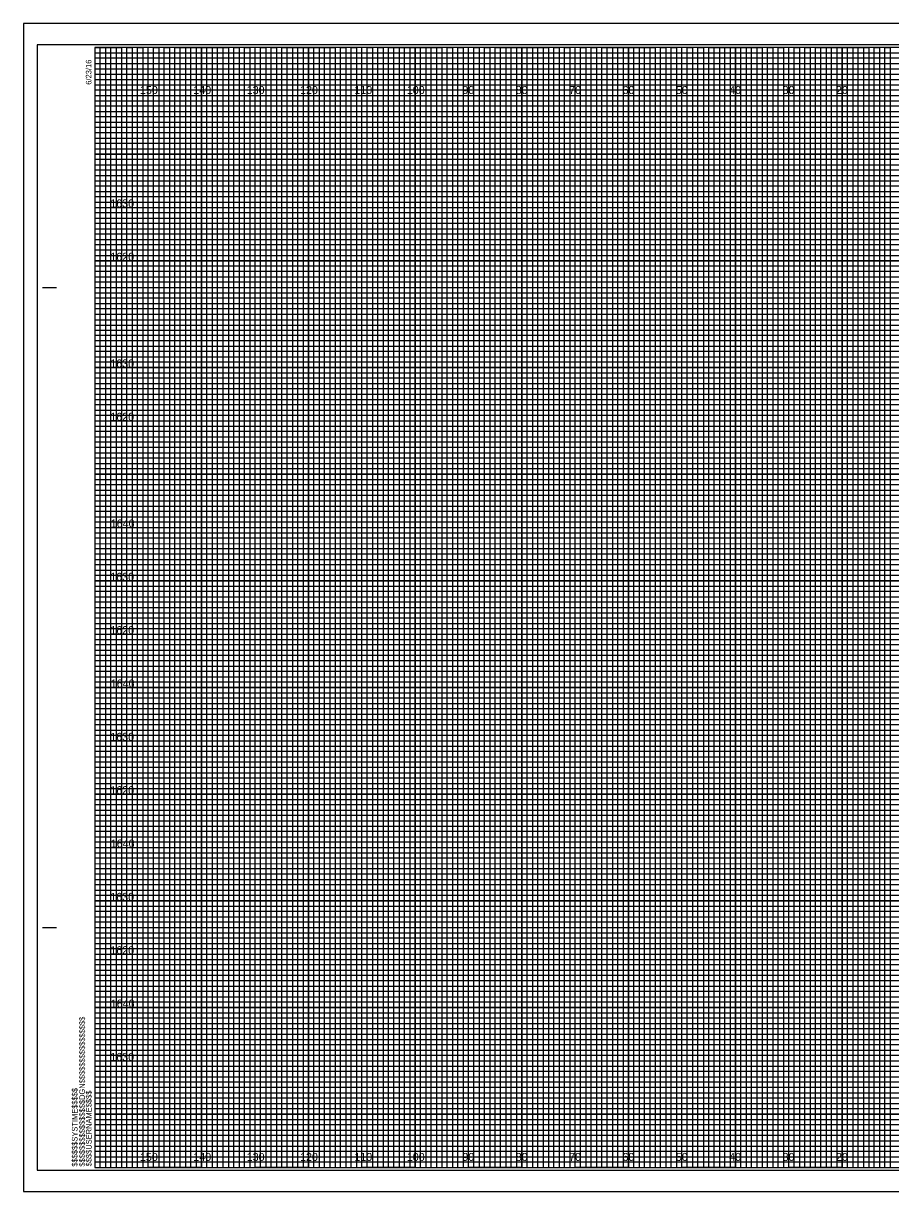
# Model space of a CAD drawing. Extents: x -423 to -87, y -23 to 1516.
# Drawn here: x -423.3 to -260.8, y 417.3 to 636.3 of the extents above; entities that cross this region are included whole.
import ezdxf

# ---------------------------------------------------------------- set-up
doc = ezdxf.new("R2010")
doc.units = 0
for name, color, linetype in [('Prop Horizontal Alignment', 7, 'Continuous'), ('Prop XS DDE', 7, 'Continuous'), ('Prop XS DDE Elevations', 7, 'Continuous'), ('Prop XS DDE Slope Text', 7, 'Continuous'), ('Prop XS Earthwork Shape', 7, 'Continuous'), ('Scratch_Level_3', 7, 'Continuous'), ('Sheet Cross Section Grid Minor 2 CELL', 7, 'Continuous'), ('Sheet Cutting Line CELL', 7, 'Continuous'), ('Sheet DOT Grid CELL', 7, 'Continuous'), ('Sheet Plot Border Inside CELL', 7, 'Continuous'), ('Sheet Plot Border Outside CELL', 7, 'Continuous')]:
    doc.layers.add(name, color=color, linetype=linetype)

msp = doc.modelspace()

# ---------------------------------------------------------------- linework, layer by layer
at = {"layer": 'Prop XS DDE'}
for points in [[(-409.86, 631.8), (-404.86, 631.8), (-404.86, 421.8), (-394.86, 421.8), (-394.86, 631.8), (-384.86, 631.8), (-384.86, 421.8), (-374.86, 421.8), (-374.86, 631.8), (-364.86, 631.8), (-364.86, 421.8), (-354.86, 421.8), (-354.86, 631.8), (-344.86, 631.8), (-344.86, 421.8), (-334.86, 421.8), (-334.86, 631.8), (-324.86, 631.8), (-324.86, 421.8), (-314.86, 421.8), (-314.86, 631.8), (-304.86, 631.8), (-304.86, 421.8), (-294.86, 421.8), (-294.86, 631.8), (-284.86, 631.8), (-284.86, 421.8), (-274.86, 421.8), (-274.86, 631.8), (-264.86, 631.8), (-264.86, 421.8), (-254.86, 421.8)], [(-409.86, 626.8), (-134.86, 626.8)], [(-409.86, 606.8), (-89.86, 606.8), (-89.86, 616.8), (-409.86, 616.8)], [(-409.86, 586.8), (-89.86, 586.8), (-89.86, 596.8), (-409.86, 596.8)], [(-409.86, 566.8), (-89.86, 566.8), (-89.86, 576.8), (-409.86, 576.8)], [(-409.86, 546.8), (-89.86, 546.8), (-89.86, 556.8), (-409.86, 556.8)], [(-409.86, 526.8), (-89.86, 526.8), (-89.86, 536.8), (-409.86, 536.8)], [(-409.86, 506.8), (-89.86, 506.8), (-89.86, 516.8), (-409.86, 516.8)], [(-409.86, 486.8), (-89.86, 486.8), (-89.86, 496.8), (-409.86, 496.8)], [(-409.86, 466.8), (-89.86, 466.8), (-89.86, 476.8), (-409.86, 476.8)], [(-409.86, 446.8), (-89.86, 446.8), (-89.86, 456.8), (-409.86, 456.8)], [(-409.86, 426.8), (-89.86, 426.8), (-89.86, 436.8), (-409.86, 436.8)]]:
    msp.add_lwpolyline(points, dxfattribs=at)
at = {"layer": 'Prop XS DDE Elevations'}
for p, q in [((-419.66, 586.8), (-417.16, 586.8)), ((-419.56, 586.8), (-417.06, 586.8)), ((-419.66, 466.8), (-417.16, 466.8)), ((-419.56, 466.8), (-417.06, 466.8)), ((-409.86, 421.8), (-409.86, 421.8)), ((-409.86, 421.8), (-409.86, 421.8)), ((-409.86, 421.8), (-409.86, 421.8)), ((-409.86, 421.8), (-409.86, 421.8)), ((-409.86, 421.8), (-409.86, 421.8)), ((-409.86, 421.8), (-409.86, 421.8)), ((-409.86, 421.8), (-409.86, 421.8))]:
    msp.add_line(p, q, dxfattribs=at)
msp.add_lwpolyline([(-89.86, 631.8), (-409.86, 631.8), (-409.86, 421.8), (-89.86, 421.8)], close=True, dxfattribs=at)
at = {"layer": 'Prop XS DDE Slope Text'}
for p, q in [((-409.86, 630.8), (-149.86, 630.8)), ((-149.86, 629.78), (-409.86, 629.78)), ((-409.86, 629.78), (-409.86, 628.8)), ((-409.86, 628.8), (-149.86, 628.8)), ((-149.86, 627.69), (-409.86, 627.69)), ((-409.86, 627.69), (-409.86, 625.8)), ((-409.86, 625.8), (-89.86, 625.8))]:
    msp.add_line(p, q, dxfattribs=at)
for points in [[(-409.86, 624.8), (-139.86, 624.8), (-89.86, 624.8), (-89.86, 623.8), (-409.86, 623.8)], [(-409.86, 622.8), (-89.86, 622.8), (-89.86, 620.8), (-409.86, 620.8)], [(-409.86, 619.8), (-89.86, 619.8), (-89.86, 618.8), (-409.86, 618.78)], [(-409.86, 617.8), (-89.86, 617.8), (-89.86, 615.8), (-409.86, 615.8)], [(-409.86, 614.8), (-89.86, 614.8), (-89.86, 613.8), (-409.86, 613.8)], [(-409.86, 612.8), (-89.86, 612.8), (-89.86, 610.8), (-409.86, 610.8)], [(-409.86, 609.8), (-89.86, 609.8), (-89.86, 608.8), (-409.86, 608.8)], [(-409.86, 607.8), (-89.86, 607.8), (-89.86, 605.8), (-409.86, 605.8)], [(-409.86, 604.8), (-89.86, 604.8), (-89.86, 603.8), (-409.86, 603.8)], [(-409.86, 602.8), (-89.86, 602.8), (-89.86, 600.8), (-409.86, 600.8)], [(-409.86, 599.8), (-89.86, 599.8), (-89.86, 598.8), (-409.86, 598.8)], [(-409.86, 597.8), (-89.86, 597.8), (-89.86, 595.75), (-89.86, 594.8), (-89.86, 593.8), (-409.86, 593.8)], [(-409.86, 595.8), (-89.86, 595.8), (-89.86, 594.8), (-409.86, 594.8)], [(-409.86, 592.8), (-89.86, 592.8), (-89.86, 590.8), (-409.86, 590.83)], [(-409.86, 590.83), (-89.86, 590.8), (-89.86, 589.8), (-409.86, 589.8)], [(-409.86, 588.8), (-89.86, 588.8), (-89.86, 587.8), (-409.86, 587.8)], [(-409.86, 585.8), (-89.86, 585.8), (-89.86, 584.8), (-409.86, 584.8)], [(-409.86, 583.8), (-89.86, 583.8), (-89.86, 582.8), (-409.86, 582.8)], [(-409.93, 580.69), (-89.86, 580.69), (-89.86, 579.68), (-409.93, 579.68)], [(-409.86, 578.8), (-89.86, 578.8), (-89.86, 577.8), (-409.86, 577.8)], [(-409.86, 575.8), (-89.86, 575.8), (-89.86, 574.8), (-409.86, 574.8)], [(-409.86, 573.8), (-89.86, 573.8), (-89.86, 572.8), (-409.86, 572.8)], [(-409.86, 570.8), (-89.86, 570.8), (-89.86, 569.8), (-409.86, 569.8)], [(-409.86, 568.8), (-89.86, 568.8), (-89.86, 567.8), (-409.86, 567.8)], [(-409.86, 565.8), (-89.86, 565.8), (-89.86, 564.8), (-409.86, 564.8)], [(-409.86, 563.8), (-89.86, 563.8), (-89.86, 562.8), (-409.86, 562.8)], [(-409.86, 560.8), (-89.86, 560.8), (-89.87, 559.78), (-409.86, 559.8)], [(-409.86, 558.8), (-89.86, 558.8), (-89.86, 557.8), (-409.86, 557.8)], [(-409.86, 555.8), (-89.86, 555.8), (-89.86, 554.8), (-409.86, 554.8)], [(-409.86, 553.8), (-89.86, 553.8), (-89.86, 552.8), (-409.86, 552.8)], [(-409.86, 550.8), (-89.86, 550.8), (-89.86, 549.8), (-409.86, 549.8)], [(-409.86, 548.8), (-89.86, 548.8), (-89.86, 547.8), (-409.86, 547.8)], [(-409.86, 545.8), (-89.86, 545.8), (-89.86, 544.8), (-409.86, 544.8)], [(-409.86, 543.8), (-89.86, 543.8), (-89.86, 542.8), (-409.86, 542.8)], [(-409.86, 540.8), (-89.86, 540.8), (-89.86, 539.8), (-409.86, 539.8)], [(-409.86, 538.79), (-89.79, 538.71), (-89.86, 537.8), (-409.86, 537.8)], [(-409.86, 535.8), (-89.86, 535.8), (-89.86, 534.8), (-409.86, 534.8)], [(-409.86, 533.8), (-89.86, 533.8), (-89.86, 532.8), (-409.86, 532.8)], [(-409.86, 530.8), (-89.86, 530.8), (-89.86, 529.8), (-409.86, 529.8)], [(-409.86, 528.8), (-89.86, 528.8), (-89.86, 527.8), (-409.86, 527.8)], [(-409.86, 525.8), (-89.86, 525.8), (-89.86, 524.8), (-409.86, 524.8)], [(-409.86, 523.8), (-89.86, 523.8), (-89.86, 522.8), (-409.86, 522.8)], [(-409.86, 520.8), (-89.86, 520.8), (-89.86, 519.8), (-409.86, 519.8)], [(-409.86, 518.8), (-89.86, 518.8), (-89.86, 517.8), (-409.86, 517.8)], [(-409.86, 515.8), (-89.86, 515.8), (-89.86, 514.8), (-409.86, 514.8)], [(-409.86, 513.8), (-89.86, 513.8), (-89.86, 512.8), (-409.86, 512.8)], [(-409.86, 510.8), (-89.86, 510.8), (-89.86, 509.8), (-409.86, 509.8)], [(-409.86, 508.8), (-89.86, 508.8), (-89.86, 507.8), (-409.86, 507.8)], [(-409.86, 505.8), (-89.86, 505.8), (-89.86, 504.8), (-409.86, 504.8)], [(-409.86, 503.8), (-89.86, 503.8), (-89.86, 502.8), (-409.86, 502.8)], [(-409.86, 500.8), (-89.86, 500.8), (-89.87, 499.78), (-409.86, 499.8)], [(-409.86, 498.8), (-89.86, 498.8), (-89.86, 497.8), (-409.86, 497.8)], [(-409.86, 495.8), (-89.86, 495.8), (-89.86, 494.8), (-409.86, 494.8)], [(-409.86, 493.8), (-89.86, 493.8), (-89.86, 492.8), (-409.86, 492.8)], [(-409.86, 490.8), (-89.86, 490.8), (-89.86, 489.8), (-409.86, 489.8)], [(-409.86, 488.8), (-89.86, 488.8), (-89.86, 487.8), (-409.86, 487.8)], [(-409.86, 485.8), (-89.86, 485.8), (-89.86, 484.8), (-409.86, 484.8)], [(-409.86, 483.8), (-89.86, 483.8), (-89.86, 482.8), (-409.86, 482.8)], [(-409.86, 480.8), (-89.86, 480.8), (-89.86, 479.8), (-409.86, 479.8)], [(-409.86, 478.79), (-89.79, 478.71), (-89.86, 477.8), (-409.86, 477.8)], [(-409.86, 475.8), (-89.86, 475.8), (-89.86, 474.8), (-409.86, 474.8)], [(-409.86, 473.8), (-89.86, 473.8), (-89.86, 472.8), (-409.86, 472.8)], [(-409.86, 470.8), (-89.86, 470.8), (-89.86, 469.8), (-409.86, 469.8)], [(-409.86, 468.8), (-89.86, 468.8), (-89.86, 467.8), (-409.86, 467.8)], [(-409.86, 465.8), (-89.86, 465.8), (-89.86, 464.8), (-409.86, 464.8)], [(-409.86, 463.8), (-89.86, 463.8), (-89.86, 462.8), (-409.86, 462.8)], [(-409.86, 460.8), (-89.86, 460.8), (-89.86, 459.8), (-409.86, 459.8)], [(-409.86, 458.8), (-89.86, 458.8), (-89.86, 457.8), (-409.86, 457.8)], [(-409.86, 455.8), (-89.86, 455.8), (-89.86, 454.8), (-409.86, 454.8)], [(-409.86, 453.8), (-89.86, 453.8), (-89.86, 452.8), (-409.86, 452.8)], [(-409.86, 450.8), (-89.86, 450.8), (-89.86, 449.8), (-409.86, 449.8)], [(-409.86, 448.8), (-89.86, 448.8), (-89.86, 447.8), (-409.86, 447.8)], [(-409.86, 445.8), (-89.86, 445.8), (-89.86, 444.8), (-409.86, 444.8)], [(-409.86, 443.8), (-89.86, 443.8), (-89.86, 442.8), (-409.86, 442.8)], [(-409.86, 440.8), (-89.86, 440.8), (-89.86, 439.8), (-409.86, 439.8)], [(-409.86, 438.8), (-89.86, 438.8), (-89.86, 437.8), (-409.86, 437.8)], [(-409.86, 435.8), (-89.86, 435.8), (-89.86, 434.8), (-409.86, 434.8)], [(-409.86, 433.8), (-89.86, 433.8), (-89.86, 432.8), (-409.86, 432.8)], [(-409.86, 430.8), (-89.86, 430.8), (-89.86, 429.8), (-409.86, 429.8)], [(-409.86, 428.8), (-89.86, 428.8), (-89.86, 427.8), (-409.86, 427.8)], [(-409.86, 425.8), (-89.86, 425.8), (-89.86, 424.8), (-409.86, 424.8)], [(-409.86, 423.8), (-89.86, 423.8), (-89.86, 422.8), (-409.86, 422.8)]]:
    msp.add_lwpolyline(points, dxfattribs=at)
at = {"layer": 'Prop XS Earthwork Shape'}
for p, q in [((-399.86, 631.8), (-409.86, 631.8)), ((-399.86, 421.8), (-399.86, 631.8)), ((-379.86, 631.8), (-389.86, 631.8)), ((-389.86, 631.8), (-389.86, 421.8)), ((-379.86, 421.8), (-379.86, 631.8)), ((-359.86, 631.8), (-369.86, 631.8)), ((-369.86, 631.8), (-369.86, 421.8)), ((-359.86, 421.8), (-359.86, 631.8)), ((-339.86, 631.8), (-349.86, 631.8)), ((-349.86, 631.8), (-349.86, 421.8)), ((-339.86, 421.8), (-339.86, 631.8)), ((-319.86, 631.8), (-329.86, 631.8)), ((-329.86, 631.8), (-329.86, 421.8)), ((-319.86, 421.8), (-319.86, 631.8)), ((-299.86, 631.8), (-309.86, 631.8)), ((-309.86, 631.8), (-309.86, 421.8)), ((-299.86, 421.8), (-299.86, 631.8)), ((-279.86, 631.8), (-289.86, 631.8)), ((-289.86, 631.8), (-289.86, 421.8)), ((-279.86, 421.8), (-279.86, 631.8)), ((-259.86, 631.8), (-269.86, 631.8)), ((-269.86, 631.8), (-269.86, 421.8)), ((-389.86, 421.8), (-399.86, 421.8)), ((-369.86, 421.8), (-379.86, 421.8)), ((-349.86, 421.8), (-359.86, 421.8)), ((-329.86, 421.8), (-339.86, 421.8)), ((-309.86, 421.8), (-319.86, 421.8)), ((-289.86, 421.8), (-299.86, 421.8)), ((-269.86, 421.8), (-279.86, 421.8))]:
    msp.add_line(p, q, dxfattribs=at)
for points in [[(-409.86, 621.8), (-89.86, 621.8), (-89.86, 611.8), (-409.86, 611.8)], [(-409.86, 601.8), (-89.86, 601.8), (-89.86, 591.8), (-409.86, 591.8)], [(-409.86, 581.8), (-89.86, 581.8), (-89.86, 571.8), (-409.86, 571.8)], [(-409.86, 561.8), (-89.86, 561.8), (-89.86, 551.8), (-409.86, 551.8)], [(-409.86, 541.8), (-89.86, 541.8), (-89.86, 531.8), (-409.86, 531.8)], [(-409.86, 521.8), (-89.86, 521.8), (-89.86, 511.8), (-409.86, 511.8)], [(-409.86, 501.8), (-89.86, 501.8), (-89.86, 491.8), (-409.86, 491.8)], [(-409.86, 481.8), (-89.86, 481.8), (-89.86, 471.8), (-409.86, 471.8)], [(-409.86, 461.8), (-89.86, 461.8), (-89.86, 451.8), (-409.86, 451.8)], [(-409.86, 441.8), (-89.86, 441.8), (-89.86, 431.8), (-409.86, 431.8)]]:
    msp.add_lwpolyline(points, dxfattribs=at)
at = {"layer": 'Sheet Cross Section Grid Minor 2 CELL'}
for points in [[(-409.86, 421.8), (-408.86, 421.8), (-408.86, 631.8), (-407.86, 631.8), (-407.86, 421.8)], [(-407.86, 421.8), (-406.86, 421.8), (-406.86, 631.8), (-405.86, 631.8), (-405.86, 421.8)], [(-404.86, 421.8), (-403.86, 421.8), (-403.86, 631.8), (-402.86, 631.8), (-402.86, 421.8)], [(-402.86, 421.8), (-401.86, 421.8), (-401.86, 631.8), (-400.86, 631.8), (-400.86, 421.8)], [(-399.86, 421.8), (-398.86, 421.8), (-398.86, 631.8), (-397.86, 631.8), (-397.86, 421.8)], [(-397.86, 421.8), (-396.86, 421.8), (-396.86, 631.8), (-395.86, 631.8), (-395.86, 421.8)], [(-394.86, 421.8), (-393.86, 421.8), (-393.86, 631.8), (-392.86, 631.8), (-392.86, 421.8)], [(-392.86, 421.8), (-391.86, 421.8), (-391.86, 631.8), (-390.86, 631.8), (-390.86, 421.8)], [(-389.86, 421.8), (-388.86, 421.8), (-388.86, 631.8), (-387.86, 631.8), (-387.86, 421.8)], [(-387.86, 421.8), (-386.86, 421.8), (-386.86, 631.8), (-385.86, 631.8), (-385.86, 421.8)], [(-384.86, 421.8), (-383.86, 421.8), (-383.86, 631.8), (-382.86, 631.8), (-382.86, 421.8)], [(-382.86, 421.8), (-381.86, 421.8), (-381.86, 631.8), (-380.86, 631.8), (-380.86, 421.8)], [(-379.86, 421.8), (-378.86, 421.8), (-378.86, 631.8), (-377.86, 631.8), (-377.86, 421.8)], [(-377.86, 421.8), (-376.86, 421.8), (-376.86, 631.8), (-375.86, 631.8), (-375.86, 421.8)], [(-374.86, 421.8), (-373.86, 421.8), (-373.86, 631.8), (-372.86, 631.8), (-372.86, 421.8)], [(-372.86, 421.8), (-371.86, 421.8), (-371.86, 631.8), (-370.86, 631.8), (-370.86, 421.8)], [(-369.86, 421.8), (-368.86, 421.8), (-368.86, 631.8), (-367.86, 631.8), (-367.86, 421.8)], [(-367.86, 421.8), (-366.86, 421.8), (-366.86, 631.8), (-365.86, 631.8), (-365.86, 421.8)], [(-364.86, 421.8), (-363.86, 421.8), (-363.86, 631.8), (-362.86, 631.8), (-362.86, 421.8)], [(-362.86, 421.8), (-361.86, 421.8), (-361.86, 631.8), (-360.86, 631.8), (-360.86, 421.8)], [(-359.86, 421.8), (-358.86, 421.8), (-358.86, 631.8), (-357.86, 631.8), (-357.86, 421.8)], [(-357.86, 421.8), (-356.86, 421.8), (-356.86, 631.8), (-355.86, 631.8), (-355.86, 421.8)], [(-354.86, 421.8), (-353.86, 421.8), (-353.86, 631.8), (-352.86, 631.8), (-352.86, 421.8)], [(-352.86, 421.8), (-351.86, 421.8), (-351.86, 631.8), (-350.86, 631.8), (-350.86, 421.8)], [(-349.86, 421.8), (-348.86, 421.8), (-348.86, 631.8), (-347.86, 631.8), (-347.86, 421.8)], [(-347.86, 421.8), (-346.86, 421.8), (-346.86, 631.8), (-345.86, 631.8), (-345.86, 421.8)], [(-344.86, 421.8), (-343.86, 421.8), (-343.86, 631.8), (-342.86, 631.8), (-342.86, 421.8)], [(-342.86, 421.8), (-341.86, 421.8), (-341.86, 631.8), (-340.86, 631.8), (-340.86, 421.8)], [(-339.86, 421.8), (-338.86, 421.8), (-338.86, 631.8), (-337.86, 631.8), (-337.86, 421.8)], [(-337.86, 421.8), (-336.86, 421.8), (-336.86, 631.8), (-335.86, 631.8), (-335.86, 421.8)], [(-334.86, 421.8), (-333.86, 421.8), (-333.86, 631.8), (-332.86, 631.8), (-332.86, 421.8)], [(-332.86, 421.8), (-331.86, 421.8), (-331.86, 631.8), (-330.86, 631.8), (-330.86, 421.8)], [(-329.86, 421.8), (-328.86, 421.8), (-328.86, 631.8), (-327.86, 631.8), (-327.86, 421.8)], [(-327.86, 421.8), (-326.86, 421.8), (-326.86, 631.8), (-325.86, 631.8), (-325.86, 421.8)], [(-324.86, 421.8), (-323.86, 421.8), (-323.86, 631.8), (-322.86, 631.8), (-322.86, 421.8)], [(-322.86, 421.8), (-321.86, 421.8), (-321.86, 631.8), (-320.86, 631.8), (-320.86, 421.8)], [(-319.86, 421.8), (-318.86, 421.8), (-318.86, 631.8), (-317.86, 631.8), (-317.86, 421.8)], [(-317.86, 421.8), (-316.86, 421.8), (-316.86, 631.8), (-315.86, 631.8), (-315.86, 421.8)], [(-314.86, 421.8), (-313.86, 421.8), (-313.86, 631.8), (-312.86, 631.8), (-312.86, 421.8)], [(-312.86, 421.8), (-311.86, 421.8), (-311.86, 631.8), (-310.86, 631.8), (-310.86, 421.8)], [(-309.86, 421.8), (-308.86, 421.8), (-308.86, 631.8), (-307.86, 631.8), (-307.86, 421.8)], [(-307.86, 421.8), (-306.86, 421.8), (-306.86, 631.8), (-305.86, 631.8), (-305.86, 421.8)], [(-304.86, 421.8), (-303.86, 421.8), (-303.86, 631.8), (-302.86, 631.8), (-302.86, 421.8)], [(-302.86, 421.8), (-301.86, 421.8), (-301.86, 631.8), (-300.86, 631.8), (-300.86, 421.8)], [(-299.86, 421.8), (-298.86, 421.8), (-298.86, 631.8), (-297.86, 631.8), (-297.86, 421.8)], [(-297.86, 421.8), (-296.86, 421.8), (-296.86, 631.8), (-295.86, 631.8), (-295.86, 421.8)], [(-294.86, 421.8), (-293.86, 421.8), (-293.86, 631.8), (-292.86, 631.8), (-292.86, 421.8)], [(-292.86, 421.8), (-291.86, 421.8), (-291.86, 631.8), (-290.86, 631.8), (-290.86, 421.8)], [(-289.86, 421.8), (-288.86, 421.8), (-288.86, 631.8), (-287.86, 631.8), (-287.86, 421.8)], [(-287.86, 421.8), (-286.86, 421.8), (-286.86, 631.8), (-285.86, 631.8), (-285.86, 421.8)], [(-284.86, 421.8), (-283.86, 421.8), (-283.86, 631.8), (-282.86, 631.8), (-282.86, 421.8)], [(-282.86, 421.8), (-281.86, 421.8), (-281.86, 631.8), (-280.86, 631.8), (-280.86, 421.8)], [(-279.86, 421.8), (-278.86, 421.8), (-278.86, 631.8), (-277.86, 631.8), (-277.86, 421.8)], [(-277.86, 421.8), (-276.86, 421.8), (-276.86, 631.8), (-275.86, 631.8), (-275.86, 421.8)], [(-274.86, 421.8), (-273.86, 421.8), (-273.86, 631.8), (-272.86, 631.8), (-272.86, 421.8)], [(-272.86, 421.8), (-271.86, 421.8), (-271.86, 631.8), (-270.86, 631.8), (-270.86, 421.8)], [(-269.86, 421.8), (-268.86, 421.8), (-268.86, 631.8), (-267.86, 631.8), (-267.86, 421.8)], [(-267.86, 421.8), (-266.86, 421.8), (-266.86, 631.8), (-265.86, 631.8), (-265.86, 421.8)], [(-264.86, 421.8), (-263.86, 421.8), (-263.86, 631.8), (-262.86, 631.8), (-262.86, 421.8)], [(-262.86, 421.8), (-261.86, 421.8), (-261.86, 631.8), (-260.86, 631.8), (-260.86, 421.8)]]:
    msp.add_lwpolyline(points, dxfattribs=at)
at = {"layer": 'Sheet Cutting Line CELL'}
for p, q in [((-86.56, 636.3), (-423.26, 636.3)), ((-423.26, 636.3), (-423.26, 417.3)), ((-423.26, 417.3), (-86.56, 417.3))]:
    msp.add_line(p, q, dxfattribs=at)
at = {"layer": 'Sheet DOT Grid CELL'}
for p, q in [((-399.86, 421.8), (-399.86, 631.8)), ((-389.86, 421.8), (-389.86, 631.8)), ((-379.86, 421.8), (-379.86, 631.8)), ((-369.86, 421.8), (-369.86, 631.8)), ((-359.86, 421.8), (-359.86, 631.8)), ((-349.86, 421.8), (-349.86, 631.8)), ((-339.86, 421.8), (-339.86, 631.8)), ((-329.86, 421.8), (-329.86, 631.8)), ((-319.86, 421.8), (-319.86, 631.8)), ((-309.86, 421.8), (-309.86, 631.8)), ((-299.86, 421.8), (-299.86, 631.8)), ((-289.86, 421.8), (-289.86, 631.8)), ((-279.86, 421.8), (-279.86, 631.8)), ((-269.86, 421.8), (-269.86, 631.8)), ((-409.86, 621.8), (-89.86, 621.8)), ((-409.86, 611.8), (-89.86, 611.8)), ((-409.86, 601.8), (-89.86, 601.8)), ((-409.86, 591.8), (-89.86, 591.8)), ((-409.86, 581.8), (-89.86, 581.8)), ((-409.86, 571.8), (-89.86, 571.8)), ((-409.86, 561.8), (-89.86, 561.8)), ((-409.86, 551.8), (-89.86, 551.8)), ((-409.86, 541.8), (-89.86, 541.8)), ((-409.86, 531.8), (-89.86, 531.8)), ((-409.86, 521.8), (-89.86, 521.8)), ((-409.86, 511.8), (-89.86, 511.8)), ((-409.86, 501.8), (-89.86, 501.8)), ((-409.86, 491.8), (-89.86, 491.8)), ((-409.86, 481.8), (-89.86, 481.8)), ((-409.86, 471.8), (-89.86, 471.8)), ((-409.86, 461.8), (-89.86, 461.8)), ((-409.86, 451.8), (-89.86, 451.8)), ((-409.86, 441.8), (-89.86, 441.8)), ((-409.86, 431.8), (-89.86, 431.8))]:
    msp.add_line(p, q, dxfattribs=at)
at = {"layer": 'Sheet Plot Border Inside CELL'}
msp.add_lwpolyline([(-420.66, 421.3), (-87.46, 421.3), (-87.46, 632.3), (-420.66, 632.3)], close=True, dxfattribs=at)
at = {"layer": 'Sheet Plot Border Outside CELL'}
msp.add_lwpolyline([(-423.26, 417.3), (-86.56, 417.3), (-86.56, 636.3), (-423.26, 636.3)], close=True, dxfattribs=at)

# ---------------------------------------------------------------- texts
at = {"layer": 'Prop Horizontal Alignment'}
for s, p in [('1630', (-406.98, 601.8)), ('1620', (-406.97, 591.8)), ('1630', (-406.98, 571.8)), ('1620', (-406.97, 561.8)), ('1640', (-406.89, 541.8)), ('1630', (-406.98, 531.8)), ('1620', (-406.97, 521.8)), ('1640', (-406.89, 511.8)), ('1630', (-406.98, 501.8)), ('1620', (-406.97, 491.8)), ('1640', (-406.89, 481.8)), ('1630', (-406.98, 471.8)), ('1620', (-406.97, 461.8)), ('1640', (-406.89, 451.8)), ('1630', (-406.98, 441.8))]:
    msp.add_text(s, height=1.5, dxfattribs=at).set_placement(p)
at = {"layer": 'Prop XS DDE Elevations'}
for s, p in [('6/23/16', (-410.51, 624.8)), ('$$$$$$$$$$$$$$$$DGN$$$$$$$$$$$$$$$$', (-411.74, 421.98)), ('$$$$$$SYSTIME$$$$$', (-413.12, 421.98)), ('$$$$USERNAME$$$$', (-410.48, 422.03))]:
    msp.add_text(s, height=1.05, rotation=90, dxfattribs=at).set_placement(p)
at = {"layer": 'Scratch_Level_3'}
for s, p in [('150', (-401.42, 623.05)), ('140', (-391.42, 623.05)), ('130', (-381.42, 623.05)), ('120', (-371.42, 623.05)), ('110', (-361.24, 623.05)), ('100', (-351.42, 623.05)), ('90', (-341.01, 623.05)), ('80', (-331.01, 623.05)), ('70', (-321.01, 623.05)), ('60', (-311.01, 623.05)), ('50', (-301.01, 623.05)), ('40', (-291.01, 623.05)), ('30', (-281.01, 623.05)), ('20', (-271.01, 623.05)), ('150', (-401.42, 423.05)), ('140', (-391.42, 423.05)), ('130', (-381.42, 423.05)), ('120', (-371.42, 423.05)), ('110', (-361.24, 423.05)), ('100', (-351.42, 423.05)), ('90', (-341.01, 423.05)), ('80', (-331.01, 423.05)), ('70', (-321.01, 423.05)), ('60', (-311.01, 423.05)), ('50', (-301.01, 423.05)), ('40', (-291.01, 423.05)), ('30', (-281.01, 423.05)), ('20', (-271.01, 423.05))]:
    msp.add_text(s, height=1.5, dxfattribs=at).set_placement(p)

doc.saveas('drawing.dxf')
